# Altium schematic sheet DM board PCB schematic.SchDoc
size 513 x 386 mm
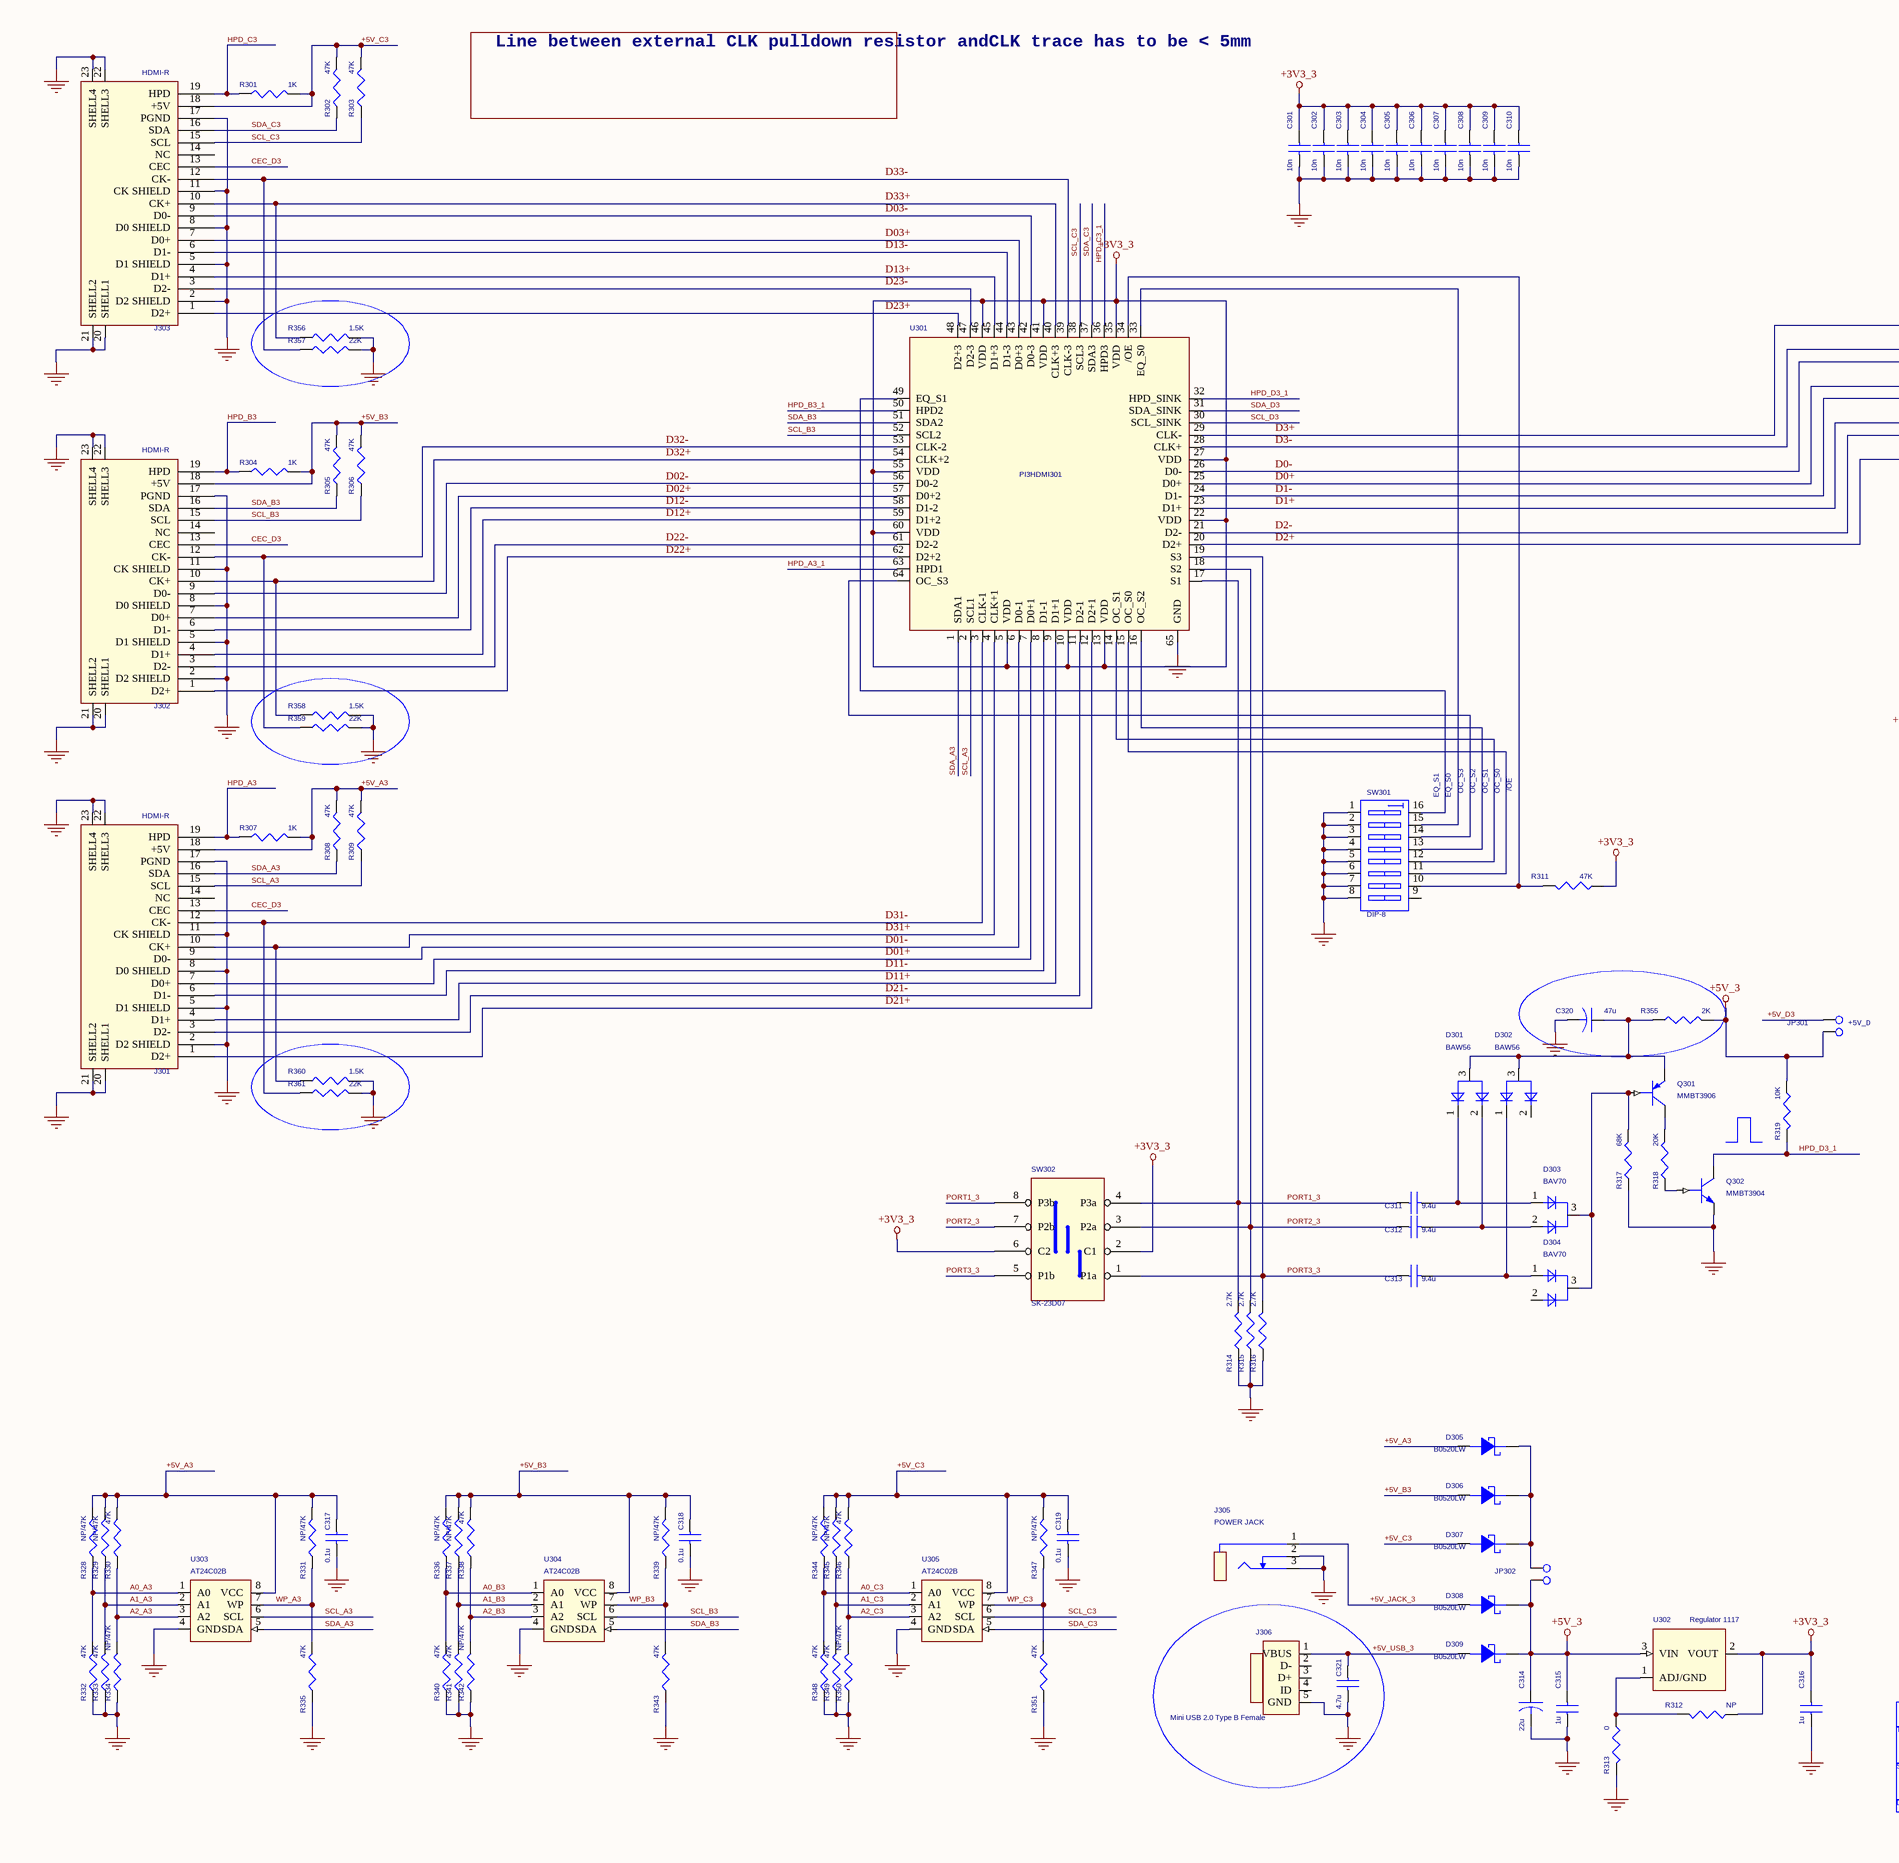
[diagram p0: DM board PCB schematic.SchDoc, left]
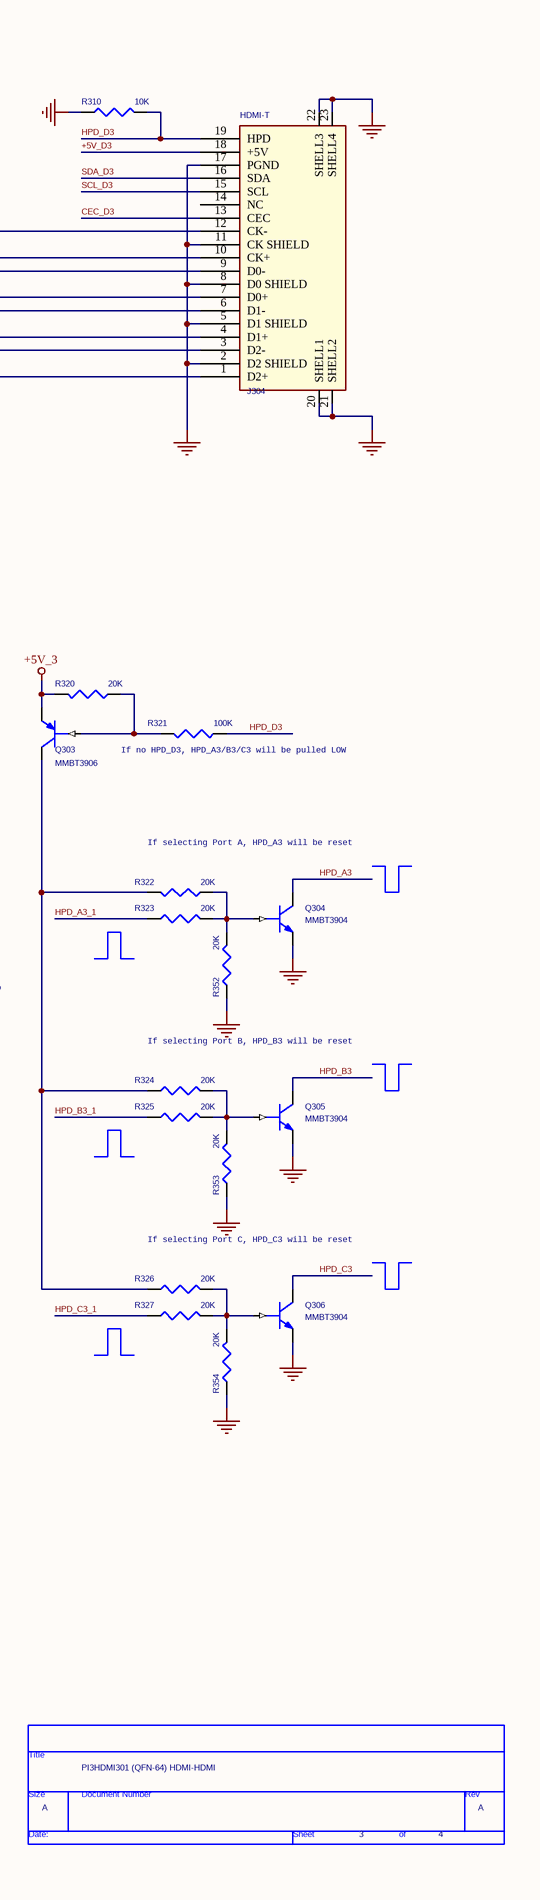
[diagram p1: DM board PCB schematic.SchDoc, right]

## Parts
*  Page Count: 4  Page Number: 3  Page Size: A  Title: PI3HDMI301 (QFN-64) HDMI-HDMI  (hidden comment: TitleBlock0)  (graphical)
C301  10n  [CAP@CC_0402]
C302  10n  [CAP@CC_0402]
C303  10n  [CAP@CC_0402]
C304  10n  [CAP@CC_0402]
C305  10n  [CAP@CC_0402]
C306  10n  [CAP@CC_0402]
C307  10n  [CAP@CC_0402]
C308  10n  [CAP@CC_0402]
C309  10n  [CAP@CC_0402]
C310  10n  [CAP@CC_0402]
C311  9.4u  [CAP@CC_1206]
C312  9.4u  [CAP@CC_1206]
C313  9.4u  [CAP@CC_1206]
C314  22u  [CAP@CT_3528]
C315  1u  [CAP@CC_0805]
C316  1u  [CAP@CC_0805]
C317  0.1u  [CAP@CC_0402]
C318  0.1u  [CAP@CC_0402]
C319  0.1u  [CAP@CC_0402]
C320  47u  [CAP@CT_3528]
C321  4.7u  [CAP@CC_0805]
D301  BAW56  [DA@SOT-23-DD]
D302  BAW56  [DA@SOT-23-DD]
D303  BAV70  [DK@SOT-23-DD]
D304  BAV70  [DK@SOT-23-DD]
D305  B0520LW  [D@SOD-123]
D306  B0520LW  [D@SOD-123]
D307  B0520LW  [D@SOD-123]
D308  B0520LW  [D@SOD-123]
D309  B0520LW  [D@SOD-123]
J301  HDMI-R  [HDMI_R@HDMI_R]
J302  HDMI-R  [HDMI_R@HDMI_R]
J303  HDMI-R  [HDMI_R@HDMI_R]
J304  HDMI-T  [HDMI_T@HDMI_T]
J305  POWER JACK  [POWERJACK@POWERJACK]
J306  Mini USB 2.0 Type B Female  [USB_B_MINI@USB_B_MINI]
JP301  CON 2  [PLUG-2PIN@2PIN-100]  (value not drawn)
JP302  CON 2  [PLUG-2PIN@2PIN-100]  (value not drawn)
Q301  MMBT3906  [Q(PNP)@SOT-23]
Q302  MMBT3904  [Q(NPN)@SOT-23]
Q303  MMBT3906  [Q(PNP)@SOT-23]
Q304  MMBT3904  [Q(NPN)@SOT-23]
Q305  MMBT3904  [Q(NPN)@SOT-23]
Q306  MMBT3904  [Q(NPN)@SOT-23]
R301  1K  [RES@R_0402]
R302  47K  [RES@R_0402]
R303  47K  [RES@R_0402]
R304  1K  [RES@R_0402]
R305  47K  [RES@R_0402]
R306  47K  [RES@R_0402]
R307  1K  [RES@R_0402]
R308  47K  [RES@R_0402]
R309  47K  [RES@R_0402]
R310  10K  [RES@R_0402]
R311  47K  [RES@R_0402]
R312  NP  [RES@R_0402]
R313  0  [RES@R_0402]
R314  2.7K  [RES@R_0402]
R315  2.7K  [RES@R_0402]
R316  2.7K  [RES@R_0402]
R317  68K  [RES@R_0402]
R318  20K  [RES@R_0402]
R319  10K  [RES@R_0402]
R320  20K  [RES@R_0402]
R321  100K  [RES@R_0402]
R322  20K  [RES@R_0402]
R323  20K  [RES@R_0402]
R324  20K  [RES@R_0402]
R325  20K  [RES@R_0402]
R326  20K  [RES@R_0402]
R327  20K  [RES@R_0402]
R328  NP/47K  [RES@R_0402]
R329  NP/47K  [RES@R_0402]
R330  47K  [RES@R_0402]
R331  NP/47K  [RES@R_0402]
R332  47K  [RES@R_0402]
R333  47K  [RES@R_0402]
R334  NP/47K  [RES@R_0402]
R335  47K  [RES@R_0402]
R336  NP/47K  [RES@R_0402]
R337  NP/47K  [RES@R_0402]
R338  47K  [RES@R_0402]
R339  NP/47K  [RES@R_0402]
R340  47K  [RES@R_0402]
R341  47K  [RES@R_0402]
R342  NP/47K  [RES@R_0402]
R343  47K  [RES@R_0402]
R344  NP/47K  [RES@R_0402]
R345  NP/47K  [RES@R_0402]
R346  47K  [RES@R_0402]
R347  NP/47K  [RES@R_0402]
R348  47K  [RES@R_0402]
R349  47K  [RES@R_0402]
R350  NP/47K  [RES@R_0402]
R351  47K  [RES@R_0402]
R352  20K  [RES@R_0402]
R353  20K  [RES@R_0402]
R354  20K  [RES@R_0402]
R355  2K  [RES@R_0402]
R356  1.5K  [RES@R_0402]
R357  22K  [RES@R_0402]
R358  1.5K  [RES@R_0402]
R359  22K  [RES@R_0402]
R360  1.5K  [RES@R_0402]
R361  22K  [RES@R_0402]
SW301  DIP-8  [SW_X8_Half_Pitch]
SW302  SK-23D07  [SWDP3T]
U301  PI3HDMI301  [QFN-64]
U302  Regulator 1117  [REG@SOT-89]
U303  AT24C02B  [SOIC-8]
U304  AT24C02B  [SOIC-8]
U305  AT24C02B  [SOIC-8]

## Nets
+3V3_3: C301.1 C302.1 C303.1 C304.1 C305.1 C306.1 C307.1 C308.1 C309.1 C310.1 C316.2 R311.1 R312.2 SW302.2(C1) SW302.6(C2) U301.5(VDD) U301.10(VDD) U301.13(VDD) U301.22(VDD) U301.27(VDD) U301.35(VDD) U301.41(VDD) U301.46(VDD) U301.55(VDD) U301.60(VDD) U302.2(VOUT)
+5V_3: C314.1 C315.2 D308.2(CATHODE) D309.2(CATHODE) JP301.2 JP302.2 Q303.2(EMITTER) R319.1 R320.2 R355.2 U302.3(VIN)
GND: C301.2 C302.2 C303.2 C304.2 C305.2 C306.2 C307.2 C308.2 C309.2 C310.2 C314.2 C315.1 C316.1 C317.2 C318.2 C319.2 C320.2 C321.2 J301.2(D2_SHIELD) J301.5(D1_SHIELD) J301.8(D0_SHIELD) J301.11(CK_SHIELD) J301.17(PGND) J301.20(SHELL1) J301.21(SHELL2) J301.22(SHELL3) J301.23(SHELL4) J302.2(D2_SHIELD) J302.5(D1_SHIELD) J302.8(D0_SHIELD) J302.11(CK_SHIELD) J302.17(PGND) J302.20(SHELL1) J302.21(SHELL2) J302.22(SHELL3) J302.23(SHELL4) J303.2(D2_SHIELD) J303.5(D1_SHIELD) J303.8(D0_SHIELD) J303.11(CK_SHIELD) J303.17(PGND) J303.20(SHELL1) J303.21(SHELL2) J303.22(SHELL3) J303.23(SHELL4) J304.2(D2_SHIELD) J304.5(D1_SHIELD) J304.8(D0_SHIELD) J304.11(CK_SHIELD) J304.17(PGND) J304.20(SHELL1) J304.21(SHELL2) J304.22(SHELL3) J304.23(SHELL4) J305.2(GND) J305.3(GND) J306.5(GND) Q302.2(EMITTER) Q304.2(EMITTER) Q305.2(EMITTER) Q306.2(EMITTER) R310.1 R313.2 R314.1 R315.1 R316.1 R317.1 R332.2 R333.2 R334.2 R335.2 R340.2 R341.2 R342.2 R343.2 R348.2 R349.2 R350.2 R351.2 R352.1 R353.1 R354.1 R356.2 R357.2 R358.2 R359.2 R360.2 R361.2 SW301.1(A1) SW301.2(A2) SW301.3(A3) SW301.4(A4) SW301.5(A5) SW301.6(A6) SW301.7(A7) SW301.8(A8) U301.65(GND) U303.4(GND) U304.4(GND) U305.4(GND)
+5V_A3: C317.1 D305.1(ANODE) J301.18(+5V) R307.2 R308.1 R309.1 R328.1 R329.1 R330.1 R331.1 U303.8(VCC)
+5V_B3: C318.1 D306.1(ANODE) J302.18(+5V) R304.2 R305.1 R306.1 R336.1 R337.1 R338.1 R339.1 U304.8(VCC)
+5V_C3: C319.1 D307.1(ANODE) J303.18(+5V) R301.2 R302.1 R303.1 R344.1 R345.1 R346.1 R347.1 U305.8(VCC)
+5V_D3: J304.18(+5V) JP301.1
+5V_JACK_3: D308.1(ANODE) J305.1
+5V_USB_3: C321.1 D309.1(ANODE) J306.1(VBUS)
A0_A3: R328.2 R332.1 U303.1(A0)
A0_B3: R336.2 R340.1 U304.1(A0)
A0_C3: R344.2 R348.1 U305.1(A0)
A1_A3: R329.2 R333.1 U303.2(A1)
A1_B3: R337.2 R341.1 U304.2(A1)
A1_C3: R345.2 R349.1 U305.2(A1)
A2_A3: R330.2 R334.1 U303.3(A2)
A2_B3: R338.2 R342.1 U304.3(A2)
A2_C3: R346.2 R350.1 U305.3(A2)
CEC_D3: J301.13(CEC) J302.13(CEC) J303.13(CEC) J304.13(CEC)
D0+: J304.7(D0+) U301.25(D0+)
D0-: J304.9(D0-) U301.26(D0-)
D01+: J301.7(D0+) U301.7(D0+1)
D1+: J304.4(D1+) U301.23(D1+)
D01-: J301.9(D0-) U301.6(D0-1)
D1-: J304.6(D1-) U301.24(D1-)
D2+: J304.1(D2+) U301.20(D2+)
D02+: J302.7(D0+) U301.57(D0+2)
D2-: J304.3(D2-) U301.21(D2-)
D02-: J302.9(D0-) U301.56(D0-2)
D3+: J304.12(CK-) U301.29(CLK-)
D03+: J303.7(D0+) U301.43(D0+3)
D3-: J304.10(CK+) U301.28(CLK+)
D03-: J303.9(D0-) U301.42(D0-3)
D11+: J301.4(D1+) U301.9(D1+1)
D11-: J301.6(D1-) U301.8(D1-1)
D12+: J302.4(D1+) U301.59(D1+2)
D12-: J302.6(D1-) U301.58(D1-2)
D13+: J303.4(D1+) U301.45(D1+3)
D13-: J303.6(D1-) U301.44(D1-3)
D21+: J301.1(D2+) U301.12(D2+1)
D21-: J301.3(D2-) U301.11(D2-1)
D22+: J302.1(D2+) U301.62(D2+2)
D22-: J302.3(D2-) U301.61(D2-2)
D23+: J303.1(D2+) U301.48(D2+3)
D23-: J303.3(D2-) U301.47(D2-3)
D31+: J301.10(CK+) R360.1 U301.4(CLK+1)
D31-: J301.12(CK-) R361.1 U301.3(CLK-1)
D32+: J302.10(CK+) R358.1 U301.54(CLK+2)
D32-: J302.12(CK-) R359.1 U301.53(CLK-2)
D33+: J303.10(CK+) R356.1 U301.40(CLK+3)
D33-: J303.12(CK-) R357.1 U301.39(CLK-3)
HPD_A3: J301.19(HPD) Q304.3(COLLECTOR) R307.1
HPD_A3_1: R323.1 U301.63(HPD1)
HPD_B3: J302.19(HPD) Q305.3(COLLECTOR) R304.1
HPD_B3_1: R325.1 U301.50(HPD2)
HPD_C3: J303.19(HPD) Q306.3(COLLECTOR) R301.1
HPD_C3_1: R327.1 U301.36(HPD3)
HPD_D3: J304.19(HPD) R310.2 R321.1
HPD_D3_1: Q302.3(COLLECTOR) R319.2 U301.32(HPD_SINK)
PORT1_3: C311.1 R314.2 SW302.4(P3a) SW302.8(P3b) U301.17(S1)
PORT2_3: C312.1 R315.2 SW302.3(P2a) SW302.7(P2b) U301.18(S2)
PORT3_3: C313.1 R316.2 SW302.1(P1a) SW302.5(P1b) U301.19(S3)
SCL_A3: J301.15(SCL) R309.2 U301.2(SCL1) U303.6(SCL)
SCL_B3: J302.15(SCL) R306.2 U301.52(SCL2) U304.6(SCL)
SCL_C3: J303.15(SCL) R303.2 U301.38(SCL3) U305.6(SCL)
SCL_D3: J304.15(SCL) U301.30(SCL_SINK)
SDA_A3: J301.16(SDA) R308.2 U301.1(SDA1) U303.5(SDA)
SDA_B3: J302.16(SDA) R305.2 U301.51(SDA2) U304.5(SDA)
SDA_C3: J303.16(SDA) R302.2 U301.37(SDA3) U305.5(SDA)
SDA_D3: J304.16(SDA) U301.31(SDA_SINK)
WP_A3: R331.2 R335.1 U303.7(WP)
WP_B3: R339.2 R343.1 U304.7(WP)
WP_C3: R347.2 R351.1 U305.7(WP)
NetC311_2: C311.2 D301.1 D303.1
NetC312_2: C312.2 D301.2 D303.2
NetC313_2: C313.2 D302.1 D304.1
NetC320_1: C320.1 D301.3 D302.3 Q301.2(EMITTER) R355.1
NetD303_3: D303.3 D304.3 Q301.1(BASE) R317.2
NetD305_2: D305.2(CATHODE) D306.2(CATHODE) D307.2(CATHODE) JP302.1
NetQ301_3: Q301.3(COLLECTOR) R318.2
NetQ302_1: Q302.1(BASE) R318.1
NetQ303_1: Q303.1(BASE) R320.1 R321.2
NetQ303_3: Q303.3(COLLECTOR) R322.2 R324.1 R326.1
NetQ304_1: Q304.1(BASE) R322.1 R323.2 R352.2
NetQ305_1: Q305.1(BASE) R324.2 R325.2 R353.2
NetQ306_1: Q306.1(BASE) R326.2 R327.2 R354.2
NetR311_2: R311.2 SW301.10(B7) U301.34(/OE)
NetR312_1: R312.1 R313.1 U302.1(ADJ/GND)
NetSW301_11: SW301.11(B6) U301.15(OC_S0)
NetSW301_12: SW301.12(B5) U301.14(OC_S1)
NetSW301_13: SW301.13(B4) U301.16(OC_S2)
NetSW301_14: SW301.14(B3) U301.64(OC_S3)
NetSW301_15: SW301.15(B2) U301.33(EQ_S0)
NetSW301_16: SW301.16(B1) U301.49(EQ_S1)

Not connected (* = marked no-connect by the designer): D302 2; D304 2; J301 14(NC); J302 14(NC); J303 14(NC); J304 14(NC); J306 2(D-) 3(D+) 4(ID); SW301 9(B8)

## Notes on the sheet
- Line between external CLK pulldown resistor andCLK trace has to be < 5mm
- (near SW301) EQ_S1
- (near SW301) EQ_S0
- OC_S3
- OC_S2
- OC_S1
- OC_S0
- /OE
- (near R321) If no HPD_D3, HPD_A3/B3/C3 will be pulled LOW
- If selecting Port A, HPD_A3 will be reset
- (near JP301) +5V_D
- If selecting Port B, HPD_B3 will be reset
- If selecting Port C, HPD_C3 will be reset

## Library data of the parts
C301-C313 C315-C319 = CAP NP_Dup1
C314 C320 = CAP
C321 = CAP NP
D301 D302 = DI dual com A
D303 D304 = DI dual com C BAV70
D305-D309 = 1N5817M/CYL
J301-J304 = CON HDMI19_A pin mame
J305 = CONN JACK_4
J306 = USB 2_0.0 Mini B Female
Q301 Q303 = T PNP BEC
Q302 Q304-Q306 = T NPN BEC
R301-R313 R317-R361 = R
R314-R316 = 11K_0
SW301 = SW DIP-8/SM_0
SW302 = SW_EG2310A
U301 = PI3HDMI301_8
U302 = Reg 117 1117 8117_0
U303-U305 = AT24C02_0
